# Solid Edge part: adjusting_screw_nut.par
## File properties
Title: Solid Edge 20
Author: vicky raina
Template: Normal.par
Last saved by: Robert a Rhodes jr
Revision: 6
Application: Solid Edge
Material: aluminum
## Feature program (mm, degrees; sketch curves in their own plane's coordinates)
sketch for "unnamed RevolvedProtrusion 1" plane through (0, 0, 0) normal (0, -1, 0) x-axis (1, 0, 0)
  line (25.4, 9.7462) -> (74.676, 9.7462)
  line (76.2, 8.2222) -> (74.676, 9.7462)
  line (76.2, -26.8298) -> (76.2, 8.2222)
  line (76.2, -26.8298) -> (74.676, -28.3538)
  line (74.676, -28.3538) -> (47.625, -28.3538)
  line (47.625, -28.3538) -> (47.625, -60.1038)
  line (47.625, -60.1038) -> (25.4, -60.1038)
  line (25.4, -60.1038) -> (25.4, 9.7462)
revolve "unnamed RevolvedProtrusion 1" add full turn 360 deg
sketch for "unnamed Hole 1" plane through (76.2, 0, 0) normal (1, 0, 0) x-axis (0, 1, 0)
  hole centre (0, -9.3038) bore radius 9.5123
hole "unnamed Hole 1" finite
pattern "unnamed Pattern 1" of "unnamed Hole 1"
pattern "unnamed Pattern 2"
sketch for "unnamed Cutout 1" plane through (0, 0, 9.7462) normal (0, 0, 1) x-axis (1, 0, 0)
extrude "unnamed Cutout 1" cut through along -normal
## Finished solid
Body 1: solid body, 16 faces, 16 edges, 4 vertices.
  Faces by surface: cylinder 7, cone 6, plane 3
  Edges by curve: circle 12, intersection 4
Bounding box of the edges (mm): 152.400 x 152.400 x 69.850, from (-76.2, -76.2, -60.1038) to (76.2, 76.2, 9.7462).
Cylindrical faces by radius (mm): R9.5123 x4, R38.1 x1, R47.625 x1, R76.2 x1
Conical faces (half-angle, radius in mm at the cone's reference point): 45 deg R74.676 x1, 45 deg R76.2 x1, 59 deg R9.5123 x4
Planar faces by outward normal: +z 1, -z 2
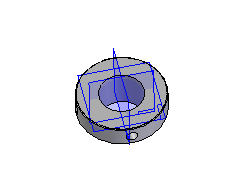
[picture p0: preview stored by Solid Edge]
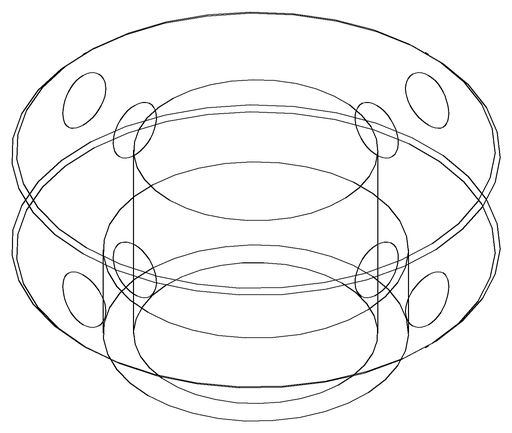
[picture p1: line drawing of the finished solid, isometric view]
